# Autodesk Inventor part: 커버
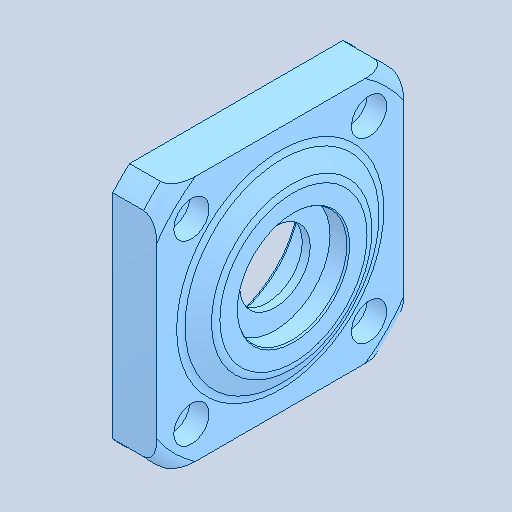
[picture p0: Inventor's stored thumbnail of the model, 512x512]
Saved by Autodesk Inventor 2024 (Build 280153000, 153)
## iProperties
Created: 2024-10
Part Number: 커버
Material: 알루미늄 6061
Document SubType Name: Modeling
Designer: user
Density: 2.7 g/cm^3
Appearance: 기본값
Author: jhkim
Sending System: Autodesk Inventor 2025
Preprocessor: ST-DEVELOPER v20
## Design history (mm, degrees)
feature "솔리드1"
node "솔리드2"
